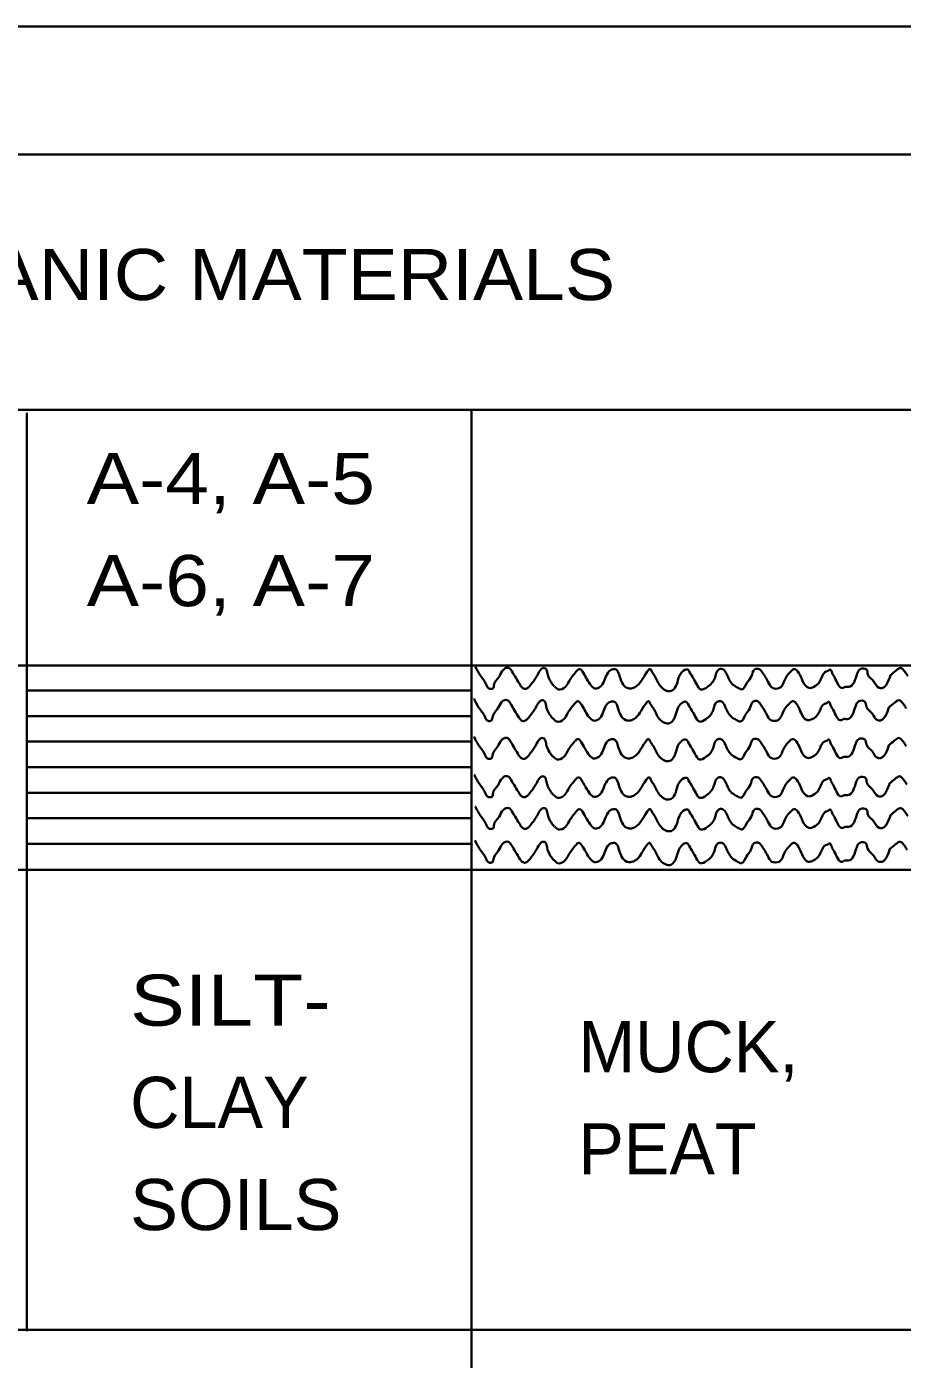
# Model space of a CAD drawing. Extents: x 2137492.6 to 2137529.1, y 2137475.8 to 2137563.
# Drawn here: x 2137500.14 to 2137501.868, y 2137553.765 to 2137556.373 of the extents above; entities that cross this region are included whole.
import ezdxf
from ezdxf.enums import TextEntityAlignment as Align

# ---------------------------------------------------------------- set-up
doc = ezdxf.new("R2010")
doc.units = 0
doc.header["$LTSCALE"] = 0.04
doc.layers.add('1', color=7, linetype='Continuous', lineweight=35)

msp = doc.modelspace()

# ---------------------------------------------------------------- linework, layer by layer
at = {"layer": '1'}
for p, q in [((2137493.171, 2137556.373), (2137501.871, 2137556.373)), ((2137493.171, 2137556.123), (2137501.871, 2137556.123)), ((2137493.171, 2137555.623), (2137501.871, 2137555.623)), ((2137500.141, 2137553.82), (2137500.141, 2137555.617)), ((2137501.011, 2137551.631), (2137501.011, 2137555.623)), ((2137493.171, 2137555.123), (2137501.871, 2137555.123)), ((2137500.141, 2137555.074), (2137501.011, 2137555.074)), ((2137501.017, 2137555.058), (2137501.016, 2137555.057)), ((2137500.141, 2137555.024), (2137501.011, 2137555.024)), ((2137500.141, 2137554.974), (2137501.011, 2137554.974)), ((2137501.017, 2137554.984), (2137501.016, 2137554.983)), ((2137500.141, 2137554.924), (2137501.011, 2137554.924)), ((2137501.018, 2137554.909), (2137501.017, 2137554.908)), ((2137500.141, 2137554.874), (2137501.011, 2137554.874)), ((2137501.02, 2137554.847), (2137501.019, 2137554.846)), ((2137500.141, 2137554.824), (2137501.011, 2137554.824)), ((2137500.141, 2137554.774), (2137501.011, 2137554.774)), ((2137501.012, 2137554.764), (2137501.011, 2137554.765)), ((2137501.013, 2137554.774), (2137501.012, 2137554.773)), ((2137501.019, 2137554.781), (2137501.018, 2137554.78)), ((2137493.171, 2137554.723), (2137501.871, 2137554.723)), ((2137493.171, 2137553.823), (2137501.871, 2137553.823))]:
    msp.add_line(p, q, dxfattribs=at)
for points in [[(2137501.173, 2137555.082), (2137501.167, 2137555.09), (2137501.16, 2137555.107), (2137501.156, 2137555.117), (2137501.152, 2137555.118), (2137501.147, 2137555.115), (2137501.14, 2137555.104), (2137501.126, 2137555.084), (2137501.121, 2137555.079), (2137501.115, 2137555.077), (2137501.111, 2137555.079), (2137501.107, 2137555.084), (2137501.09, 2137555.112), (2137501.086, 2137555.117), (2137501.084, 2137555.118), (2137501.079, 2137555.118), (2137501.073, 2137555.114), (2137501.065, 2137555.101), (2137501.055, 2137555.084), (2137501.054, 2137555.079), (2137501.048, 2137555.077), (2137501.043, 2137555.08), (2137501.04, 2137555.086), (2137501.028, 2137555.104), (2137501.019, 2137555.12)], [(2137501.174, 2137555.082), (2137501.181, 2137555.076), (2137501.195, 2137555.081), (2137501.202, 2137555.092), (2137501.216, 2137555.111), (2137501.222, 2137555.116), (2137501.23, 2137555.108), (2137501.237, 2137555.096), (2137501.245, 2137555.084), (2137501.253, 2137555.078), (2137501.263, 2137555.081), (2137501.271, 2137555.093), (2137501.286, 2137555.115), (2137501.294, 2137555.115), (2137501.3, 2137555.105), (2137501.316, 2137555.079), (2137501.324, 2137555.078), (2137501.332, 2137555.081), (2137501.355, 2137555.111), (2137501.361, 2137555.116), (2137501.364, 2137555.111), (2137501.37, 2137555.102), (2137501.382, 2137555.081), (2137501.402, 2137555.073), (2137501.409, 2137555.079), (2137501.423, 2137555.11), (2137501.434, 2137555.115), (2137501.438, 2137555.11), (2137501.452, 2137555.086), (2137501.46, 2137555.076), (2137501.473, 2137555.081), (2137501.487, 2137555.098), (2137501.495, 2137555.115), (2137501.502, 2137555.116), (2137501.51, 2137555.107), (2137501.522, 2137555.086), (2137501.533, 2137555.079), (2137501.54, 2137555.076), (2137501.55, 2137555.089), (2137501.559, 2137555.102), (2137501.565, 2137555.115), (2137501.574, 2137555.116), (2137501.579, 2137555.111), (2137501.592, 2137555.09), (2137501.6, 2137555.079), (2137501.614, 2137555.079), (2137501.626, 2137555.099), (2137501.638, 2137555.113), (2137501.642, 2137555.116), (2137501.652, 2137555.108), (2137501.659, 2137555.093), (2137501.671, 2137555.079), (2137501.681, 2137555.081), (2137501.693, 2137555.092), (2137501.705, 2137555.111), (2137501.71, 2137555.113), (2137501.713, 2137555.115), (2137501.717, 2137555.108), (2137501.722, 2137555.099), (2137501.738, 2137555.079), (2137501.742, 2137555.081), (2137501.749, 2137555.081), (2137501.766, 2137555.107), (2137501.772, 2137555.116), (2137501.784, 2137555.115), (2137501.787, 2137555.105), (2137501.798, 2137555.092), (2137501.809, 2137555.079), (2137501.816, 2137555.079), (2137501.824, 2137555.087), (2137501.831, 2137555.104)], [(2137501.831, 2137555.104), (2137501.842, 2137555.113), (2137501.851, 2137555.118), (2137501.859, 2137555.111), (2137501.865, 2137555.102)], [(2137501.17, 2137555.019), (2137501.164, 2137555.027), (2137501.157, 2137555.044), (2137501.153, 2137555.054), (2137501.149, 2137555.055), (2137501.144, 2137555.052), (2137501.137, 2137555.041), (2137501.123, 2137555.021), (2137501.118, 2137555.016), (2137501.112, 2137555.014), (2137501.108, 2137555.016), (2137501.104, 2137555.021), (2137501.087, 2137555.049), (2137501.083, 2137555.054), (2137501.081, 2137555.055), (2137501.076, 2137555.055), (2137501.07, 2137555.051), (2137501.062, 2137555.038), (2137501.052, 2137555.021), (2137501.051, 2137555.016), (2137501.045, 2137555.014), (2137501.04, 2137555.017), (2137501.037, 2137555.023), (2137501.025, 2137555.041), (2137501.016, 2137555.057)], [(2137501.171, 2137555.019), (2137501.178, 2137555.013), (2137501.192, 2137555.018), (2137501.199, 2137555.029), (2137501.213, 2137555.048), (2137501.219, 2137555.053), (2137501.227, 2137555.045), (2137501.234, 2137555.033), (2137501.242, 2137555.021), (2137501.25, 2137555.015), (2137501.26, 2137555.018), (2137501.268, 2137555.03), (2137501.283, 2137555.052), (2137501.291, 2137555.052), (2137501.297, 2137555.042), (2137501.313, 2137555.016), (2137501.321, 2137555.015), (2137501.329, 2137555.018), (2137501.352, 2137555.048), (2137501.358, 2137555.053), (2137501.361, 2137555.048), (2137501.367, 2137555.039), (2137501.379, 2137555.018), (2137501.399, 2137555.01), (2137501.406, 2137555.016), (2137501.42, 2137555.047), (2137501.431, 2137555.052), (2137501.435, 2137555.047), (2137501.449, 2137555.023), (2137501.457, 2137555.013), (2137501.47, 2137555.018), (2137501.484, 2137555.035), (2137501.492, 2137555.052), (2137501.499, 2137555.053), (2137501.507, 2137555.044), (2137501.519, 2137555.023), (2137501.53, 2137555.016), (2137501.537, 2137555.013), (2137501.547, 2137555.026), (2137501.556, 2137555.039), (2137501.562, 2137555.052), (2137501.571, 2137555.053), (2137501.576, 2137555.048), (2137501.589, 2137555.027), (2137501.597, 2137555.016), (2137501.611, 2137555.016), (2137501.623, 2137555.036), (2137501.635, 2137555.05), (2137501.639, 2137555.053), (2137501.649, 2137555.045), (2137501.656, 2137555.03), (2137501.668, 2137555.016), (2137501.678, 2137555.018), (2137501.69, 2137555.029), (2137501.702, 2137555.048), (2137501.707, 2137555.05), (2137501.71, 2137555.052), (2137501.714, 2137555.045), (2137501.719, 2137555.036), (2137501.735, 2137555.016), (2137501.739, 2137555.018), (2137501.746, 2137555.018), (2137501.763, 2137555.044), (2137501.769, 2137555.053), (2137501.781, 2137555.052), (2137501.784, 2137555.042), (2137501.795, 2137555.029), (2137501.806, 2137555.016), (2137501.813, 2137555.016), (2137501.821, 2137555.024), (2137501.828, 2137555.041)], [(2137501.828, 2137555.041), (2137501.839, 2137555.05), (2137501.848, 2137555.055), (2137501.856, 2137555.048), (2137501.862, 2137555.039)], [(2137501.17, 2137554.945), (2137501.164, 2137554.953), (2137501.157, 2137554.97), (2137501.153, 2137554.98), (2137501.149, 2137554.981), (2137501.144, 2137554.978), (2137501.137, 2137554.967), (2137501.123, 2137554.947), (2137501.118, 2137554.942), (2137501.112, 2137554.94), (2137501.108, 2137554.942), (2137501.104, 2137554.947), (2137501.087, 2137554.975), (2137501.083, 2137554.98), (2137501.081, 2137554.981), (2137501.076, 2137554.981), (2137501.07, 2137554.977), (2137501.062, 2137554.964), (2137501.052, 2137554.947), (2137501.051, 2137554.942), (2137501.045, 2137554.94), (2137501.04, 2137554.943), (2137501.037, 2137554.949), (2137501.025, 2137554.967), (2137501.016, 2137554.983)], [(2137501.171, 2137554.945), (2137501.178, 2137554.939), (2137501.192, 2137554.944), (2137501.199, 2137554.955), (2137501.213, 2137554.974), (2137501.219, 2137554.979), (2137501.227, 2137554.971), (2137501.234, 2137554.959), (2137501.242, 2137554.947), (2137501.25, 2137554.941), (2137501.26, 2137554.944), (2137501.268, 2137554.956), (2137501.283, 2137554.978), (2137501.291, 2137554.978), (2137501.297, 2137554.968), (2137501.313, 2137554.942), (2137501.321, 2137554.941), (2137501.329, 2137554.944), (2137501.352, 2137554.974), (2137501.358, 2137554.979), (2137501.361, 2137554.974), (2137501.367, 2137554.965), (2137501.379, 2137554.944), (2137501.399, 2137554.936), (2137501.406, 2137554.942), (2137501.42, 2137554.973), (2137501.431, 2137554.978), (2137501.435, 2137554.973), (2137501.449, 2137554.949), (2137501.457, 2137554.939), (2137501.47, 2137554.944), (2137501.484, 2137554.961), (2137501.492, 2137554.978), (2137501.499, 2137554.979), (2137501.507, 2137554.97), (2137501.519, 2137554.949), (2137501.53, 2137554.942), (2137501.537, 2137554.939), (2137501.547, 2137554.952), (2137501.556, 2137554.965), (2137501.562, 2137554.978), (2137501.571, 2137554.979), (2137501.576, 2137554.974), (2137501.589, 2137554.953), (2137501.597, 2137554.942), (2137501.611, 2137554.942), (2137501.623, 2137554.962), (2137501.635, 2137554.976), (2137501.639, 2137554.979), (2137501.649, 2137554.971), (2137501.656, 2137554.956), (2137501.668, 2137554.942), (2137501.678, 2137554.944), (2137501.69, 2137554.955), (2137501.702, 2137554.974), (2137501.707, 2137554.976), (2137501.71, 2137554.978), (2137501.714, 2137554.971), (2137501.719, 2137554.962), (2137501.735, 2137554.942), (2137501.739, 2137554.944), (2137501.746, 2137554.944), (2137501.763, 2137554.97), (2137501.769, 2137554.979), (2137501.781, 2137554.978), (2137501.784, 2137554.968), (2137501.795, 2137554.955), (2137501.806, 2137554.942), (2137501.813, 2137554.942), (2137501.821, 2137554.95), (2137501.828, 2137554.967)], [(2137501.828, 2137554.967), (2137501.839, 2137554.976), (2137501.848, 2137554.981), (2137501.856, 2137554.974), (2137501.862, 2137554.965)], [(2137501.171, 2137554.87), (2137501.165, 2137554.878), (2137501.158, 2137554.895), (2137501.154, 2137554.905), (2137501.15, 2137554.906), (2137501.145, 2137554.903), (2137501.138, 2137554.892), (2137501.124, 2137554.872), (2137501.119, 2137554.867), (2137501.113, 2137554.865), (2137501.109, 2137554.867), (2137501.105, 2137554.872), (2137501.088, 2137554.9), (2137501.084, 2137554.905), (2137501.082, 2137554.906), (2137501.077, 2137554.906), (2137501.071, 2137554.902), (2137501.063, 2137554.889), (2137501.053, 2137554.872), (2137501.052, 2137554.867), (2137501.046, 2137554.865), (2137501.041, 2137554.868), (2137501.038, 2137554.874), (2137501.026, 2137554.892), (2137501.017, 2137554.908)], [(2137501.172, 2137554.87), (2137501.179, 2137554.864), (2137501.193, 2137554.869), (2137501.2, 2137554.88), (2137501.214, 2137554.899), (2137501.22, 2137554.904), (2137501.228, 2137554.896), (2137501.235, 2137554.884), (2137501.243, 2137554.872), (2137501.251, 2137554.866), (2137501.261, 2137554.869), (2137501.269, 2137554.881), (2137501.284, 2137554.903), (2137501.292, 2137554.903), (2137501.298, 2137554.893), (2137501.314, 2137554.867), (2137501.322, 2137554.866), (2137501.33, 2137554.869), (2137501.353, 2137554.899), (2137501.359, 2137554.904), (2137501.362, 2137554.899), (2137501.368, 2137554.89), (2137501.38, 2137554.869), (2137501.4, 2137554.861), (2137501.407, 2137554.867), (2137501.421, 2137554.898), (2137501.432, 2137554.903), (2137501.436, 2137554.898), (2137501.45, 2137554.874), (2137501.458, 2137554.864), (2137501.471, 2137554.869), (2137501.485, 2137554.886), (2137501.493, 2137554.903), (2137501.5, 2137554.904), (2137501.508, 2137554.895), (2137501.52, 2137554.874), (2137501.531, 2137554.867), (2137501.538, 2137554.864), (2137501.548, 2137554.877), (2137501.557, 2137554.89), (2137501.563, 2137554.903), (2137501.572, 2137554.904), (2137501.577, 2137554.899), (2137501.59, 2137554.878), (2137501.598, 2137554.867), (2137501.612, 2137554.867), (2137501.624, 2137554.887), (2137501.636, 2137554.901), (2137501.64, 2137554.904), (2137501.65, 2137554.896), (2137501.657, 2137554.881), (2137501.669, 2137554.867), (2137501.679, 2137554.869), (2137501.691, 2137554.88), (2137501.703, 2137554.899), (2137501.708, 2137554.901), (2137501.711, 2137554.903), (2137501.715, 2137554.896), (2137501.72, 2137554.887), (2137501.736, 2137554.867), (2137501.74, 2137554.869), (2137501.747, 2137554.869), (2137501.764, 2137554.895), (2137501.77, 2137554.904), (2137501.782, 2137554.903), (2137501.785, 2137554.893), (2137501.796, 2137554.88), (2137501.807, 2137554.867), (2137501.814, 2137554.867), (2137501.822, 2137554.875), (2137501.829, 2137554.892)], [(2137501.829, 2137554.892), (2137501.84, 2137554.901), (2137501.849, 2137554.906), (2137501.857, 2137554.899), (2137501.863, 2137554.89)], [(2137501.173, 2137554.808), (2137501.167, 2137554.816), (2137501.16, 2137554.833), (2137501.156, 2137554.843), (2137501.152, 2137554.844), (2137501.147, 2137554.841), (2137501.14, 2137554.83), (2137501.126, 2137554.81), (2137501.121, 2137554.805), (2137501.115, 2137554.803), (2137501.111, 2137554.805), (2137501.107, 2137554.81), (2137501.09, 2137554.838), (2137501.086, 2137554.843), (2137501.084, 2137554.844), (2137501.079, 2137554.844), (2137501.073, 2137554.84), (2137501.065, 2137554.827), (2137501.055, 2137554.81), (2137501.054, 2137554.805), (2137501.048, 2137554.803), (2137501.043, 2137554.806), (2137501.04, 2137554.812), (2137501.028, 2137554.83), (2137501.019, 2137554.846)], [(2137501.174, 2137554.808), (2137501.181, 2137554.802), (2137501.195, 2137554.807), (2137501.202, 2137554.818), (2137501.216, 2137554.837), (2137501.222, 2137554.842), (2137501.23, 2137554.834), (2137501.237, 2137554.822), (2137501.245, 2137554.81), (2137501.253, 2137554.804), (2137501.263, 2137554.807), (2137501.271, 2137554.819), (2137501.286, 2137554.841), (2137501.294, 2137554.841), (2137501.3, 2137554.831), (2137501.316, 2137554.805), (2137501.324, 2137554.804), (2137501.332, 2137554.807), (2137501.355, 2137554.837), (2137501.361, 2137554.842), (2137501.364, 2137554.837), (2137501.37, 2137554.828), (2137501.382, 2137554.807), (2137501.402, 2137554.799), (2137501.409, 2137554.805), (2137501.423, 2137554.836), (2137501.434, 2137554.841), (2137501.438, 2137554.836), (2137501.452, 2137554.812), (2137501.46, 2137554.802), (2137501.473, 2137554.807), (2137501.487, 2137554.824), (2137501.495, 2137554.841), (2137501.502, 2137554.842), (2137501.51, 2137554.833), (2137501.522, 2137554.812), (2137501.533, 2137554.805), (2137501.54, 2137554.802), (2137501.55, 2137554.815), (2137501.559, 2137554.828), (2137501.565, 2137554.841), (2137501.574, 2137554.842), (2137501.579, 2137554.837), (2137501.592, 2137554.816), (2137501.6, 2137554.805), (2137501.614, 2137554.805), (2137501.626, 2137554.825), (2137501.638, 2137554.839), (2137501.642, 2137554.842), (2137501.652, 2137554.834), (2137501.659, 2137554.819), (2137501.671, 2137554.805), (2137501.681, 2137554.807), (2137501.693, 2137554.818), (2137501.705, 2137554.837), (2137501.71, 2137554.839), (2137501.713, 2137554.841), (2137501.717, 2137554.834), (2137501.722, 2137554.825), (2137501.738, 2137554.805), (2137501.742, 2137554.807), (2137501.749, 2137554.807), (2137501.766, 2137554.833), (2137501.772, 2137554.842), (2137501.784, 2137554.841), (2137501.787, 2137554.831), (2137501.798, 2137554.818), (2137501.809, 2137554.805), (2137501.816, 2137554.805), (2137501.824, 2137554.813), (2137501.831, 2137554.83)], [(2137501.831, 2137554.83), (2137501.842, 2137554.839), (2137501.851, 2137554.844), (2137501.859, 2137554.837), (2137501.865, 2137554.828)], [(2137501.172, 2137554.742), (2137501.166, 2137554.75), (2137501.159, 2137554.767), (2137501.155, 2137554.777), (2137501.151, 2137554.778), (2137501.146, 2137554.775), (2137501.139, 2137554.764), (2137501.125, 2137554.744), (2137501.12, 2137554.739), (2137501.114, 2137554.737), (2137501.11, 2137554.739), (2137501.106, 2137554.744), (2137501.089, 2137554.772), (2137501.085, 2137554.777), (2137501.083, 2137554.778), (2137501.078, 2137554.778), (2137501.072, 2137554.774), (2137501.064, 2137554.761), (2137501.054, 2137554.744), (2137501.053, 2137554.739), (2137501.047, 2137554.737), (2137501.042, 2137554.74), (2137501.039, 2137554.746), (2137501.027, 2137554.764), (2137501.018, 2137554.78)], [(2137501.173, 2137554.742), (2137501.18, 2137554.736), (2137501.194, 2137554.741), (2137501.201, 2137554.752), (2137501.215, 2137554.771), (2137501.221, 2137554.776), (2137501.229, 2137554.768), (2137501.236, 2137554.756), (2137501.244, 2137554.744), (2137501.252, 2137554.738), (2137501.262, 2137554.741), (2137501.27, 2137554.753), (2137501.285, 2137554.775), (2137501.293, 2137554.775), (2137501.299, 2137554.765), (2137501.315, 2137554.739), (2137501.323, 2137554.738), (2137501.331, 2137554.741), (2137501.354, 2137554.771), (2137501.36, 2137554.776), (2137501.363, 2137554.771), (2137501.369, 2137554.762), (2137501.381, 2137554.741), (2137501.401, 2137554.733), (2137501.408, 2137554.739), (2137501.422, 2137554.77), (2137501.433, 2137554.775), (2137501.437, 2137554.77), (2137501.451, 2137554.746), (2137501.459, 2137554.736), (2137501.472, 2137554.741), (2137501.486, 2137554.758), (2137501.494, 2137554.775), (2137501.501, 2137554.776), (2137501.509, 2137554.767), (2137501.521, 2137554.746), (2137501.532, 2137554.739), (2137501.539, 2137554.736), (2137501.549, 2137554.749), (2137501.558, 2137554.762), (2137501.564, 2137554.775), (2137501.573, 2137554.776), (2137501.578, 2137554.771), (2137501.591, 2137554.75), (2137501.599, 2137554.739), (2137501.613, 2137554.739), (2137501.625, 2137554.759), (2137501.637, 2137554.773), (2137501.641, 2137554.776), (2137501.651, 2137554.768), (2137501.658, 2137554.753), (2137501.67, 2137554.739), (2137501.68, 2137554.741), (2137501.692, 2137554.752), (2137501.704, 2137554.771), (2137501.709, 2137554.773), (2137501.712, 2137554.775), (2137501.716, 2137554.768), (2137501.721, 2137554.759), (2137501.737, 2137554.739), (2137501.741, 2137554.741), (2137501.748, 2137554.741), (2137501.765, 2137554.767), (2137501.771, 2137554.776), (2137501.783, 2137554.775), (2137501.786, 2137554.765), (2137501.797, 2137554.752), (2137501.808, 2137554.739), (2137501.815, 2137554.739), (2137501.823, 2137554.747), (2137501.83, 2137554.764)], [(2137501.83, 2137554.764), (2137501.841, 2137554.773), (2137501.85, 2137554.778), (2137501.858, 2137554.771), (2137501.864, 2137554.762)]]:
    msp.add_spline(points, degree=3, dxfattribs=at)

# ---------------------------------------------------------------- texts
at = {"layer": '1', "width": 1.1}
msp.add_text('ORGANIC MATERIALS', height=0.1, dxfattribs=at).set_placement((2137500.5115, 2137555.838), align=Align.CENTER)
at = {"layer": '1'}
for s, width, p in [('A-4, A-5', 1.15, (2137500.258, 2137555.439)), ('A-6, A-7', 1.15, (2137500.258, 2137555.239)), ('SILT-', 1.2, (2137500.343, 2137554.418)), ('SOILS', 1.05, (2137500.343, 2137554.018))]:
    msp.add_text(s, height=0.1, dxfattribs=dict(at, width=width)).set_placement(p)
for s, p in [('MUCK,', (2137501.22, 2137554.327)), ('CLAY', (2137500.343, 2137554.218)), ('PEAT', (2137501.22, 2137554.127))]:
    msp.add_text(s, height=0.1, dxfattribs=at).set_placement(p)

doc.saveas('drawing.dxf')
